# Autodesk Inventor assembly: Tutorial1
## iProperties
Created: 2004-07
Part Number: Tutorial1
Document SubType Name: Weldment
Designer: CADCIM Technologies
Manufacturer: Standard
Standards Organization: Custom
Author: CADCIM Technologies
